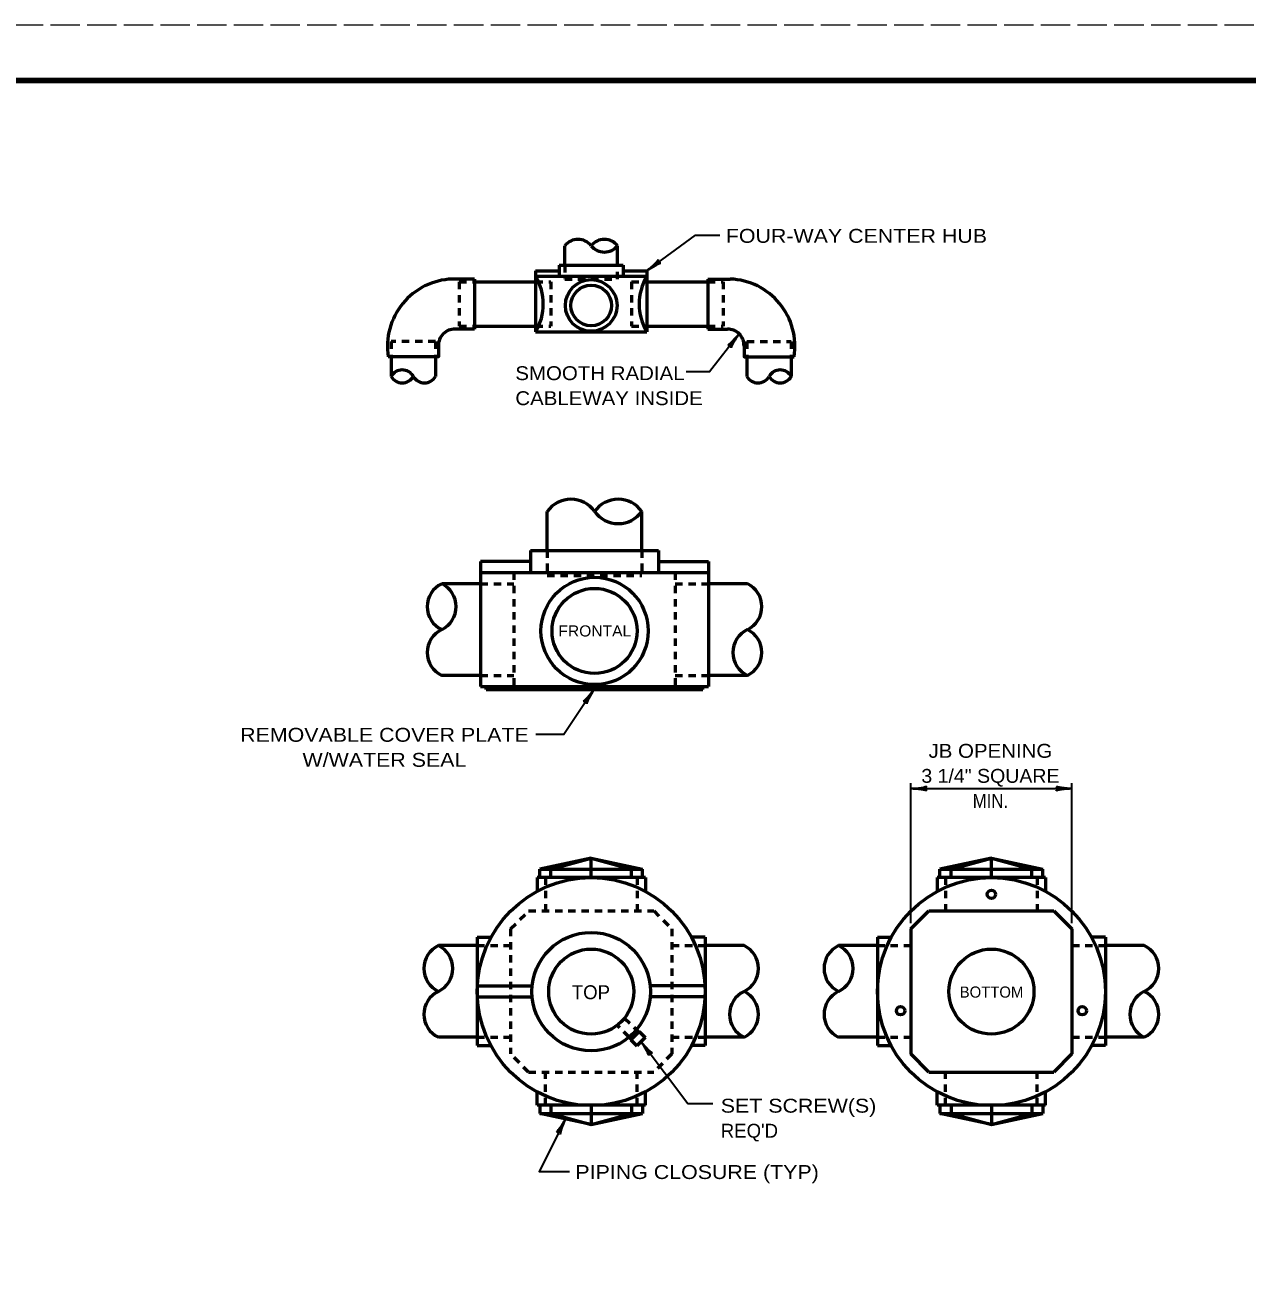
# Model space of a CAD drawing. Extents: x -295 to 385, y -102 to 338.
# Drawn here: x -75.4 to 144.5, y 114.2 to 338.4 of the extents above; entities that cross this region are included whole.
import ezdxf
from ezdxf.enums import TextEntityAlignment as Align

# ---------------------------------------------------------------- set-up
doc = ezdxf.new("R2010")
doc.units = 0
doc.header["$LTSCALE"] = 0.88
doc.linetypes.add('LONG_DASHED', pattern=[7.5, 6, -1.5])
doc.linetypes.add('SHORT_DASHED', pattern=[2.7, 1.5, -1.2])
doc.layers.add('1', color=7, linetype='Continuous', lineweight=53)
doc.layers.add('61', color=7, linetype='Continuous', lineweight=35)

msp = doc.modelspace()

# ---------------------------------------------------------------- linework, layer by layer
at = {"layer": '1'}
for p, q in [((21.7247, 295.2439), (21.7247, 298.7439)), ((31.2247, 295.2439), (31.2247, 298.7439)), ((16.4747, 294.2439), (16.4747, 283.2439)), ((16.4747, 294.2439), (20.7247, 294.2439)), ((20.7247, 295.2439), (32.2247, 295.2439)), ((20.7247, 295.2439), (20.7247, 293.2439)), ((32.2247, 295.2439), (32.2247, 293.2439)), ((32.2247, 294.2439), (36.4747, 294.2439)), ((36.4747, 294.2439), (36.4747, 283.2439)), ((5.4747, 292.7439), (1.4747, 292.7439)), ((5.4747, 292.7439), (5.4747, 283.7439)), ((5.4747, 292.2439), (16.4747, 292.2439)), ((16.4747, 293.2439), (36.4747, 293.2439)), ((36.4747, 292.2439), (47.4747, 292.2439)), ((47.4747, 292.7439), (47.4747, 283.7439)), ((47.4747, 292.7439), (51.4747, 292.7439)), ((5.4747, 283.7439), (1.9747, 283.7439)), ((5.4747, 284.2439), (16.4747, 284.2439)), ((16.4747, 283.2439), (36.4747, 283.2439)), ((36.4747, 284.2439), (47.4747, 284.2439)), ((47.4747, 283.7439), (50.9747, 283.7439)), ((-9.5253, 278.7439), (-9.5253, 275.2439)), ((-1.5253, 278.7439), (-1.5253, 275.2439)), ((54.4747, 278.7439), (54.4747, 275.2439)), ((62.4747, 278.7439), (62.4747, 275.2439)), ((18.5817, 243.9539), (18.5817, 250.9539)), ((35.5817, 243.9539), (35.5817, 250.9539)), ((15.5817, 243.9539), (38.5817, 243.9539)), ((15.5817, 243.9539), (15.5817, 239.9539)), ((38.5817, 243.9539), (38.5817, 239.9539)), ((15.5817, 241.9539), (6.5817, 241.9539)), ((6.5817, 241.9539), (6.5817, 219.4539)), ((38.5817, 241.9539), (47.5817, 241.9539)), ((47.5817, 241.9539), (47.5817, 219.4539)), ((6.5817, 237.9539), (-0.4183, 237.9539)), ((6.5817, 239.9539), (47.5817, 239.9539)), ((54.5817, 237.9539), (47.5817, 237.9539)), ((6.5817, 221.4539), (-0.4183, 221.4539)), ((54.5817, 221.4539), (47.5817, 221.4539)), ((6.5817, 219.4539), (47.5817, 219.4539)), ((7.5817, 218.9539), (7.5817, 219.4539)), ((7.5817, 218.9539), (46.5817, 218.9539)), ((46.5817, 218.9539), (46.5817, 219.4539)), ((26.4747, 188.5908), (35.7247, 186.5908)), ((98.4747, 188.5908), (107.7247, 186.5908)), ((17.2247, 185.0908), (17.2247, 186.5908)), ((17.2247, 186.5908), (35.7247, 186.5908)), ((19.2247, 185.0908), (19.2247, 186.5908)), ((33.7247, 185.0908), (33.7247, 186.5908)), ((35.7247, 185.0908), (35.7247, 186.5908)), ((89.2247, 185.0908), (89.2247, 186.5908)), ((89.2247, 186.5908), (107.7247, 186.5908)), ((91.2247, 185.0908), (91.2247, 186.5908)), ((105.7247, 185.0908), (105.7247, 186.5908)), ((107.7247, 185.0908), (107.7247, 186.5908)), ((16.7247, 185.0908), (16.7247, 182.6437)), ((36.2247, 185.0908), (16.7247, 185.0908)), ((36.2247, 185.0908), (36.2247, 182.6038)), ((88.7247, 185.0908), (88.7247, 182.6437)), ((108.2247, 185.0908), (88.7247, 185.0908)), ((108.2247, 185.0908), (108.2247, 182.6038)), ((83.9747, 175.8777), (87.2247, 179.0908)), ((87.2247, 179.0908), (109.7247, 179.0908)), ((109.7247, 179.0908), (112.9747, 175.8777)), ((83.9747, 175.8777), (83.9747, 153.3777)), ((112.9747, 175.8777), (112.9747, 153.3777)), ((5.9747, 172.8777), (-1.0253, 172.8777)), ((5.9747, 174.3777), (5.9747, 154.8777)), ((5.9747, 174.3777), (8.4617, 174.3777)), ((46.9747, 174.3777), (44.4877, 174.3777)), ((46.9747, 174.3777), (46.9747, 154.8777)), ((53.9747, 172.8777), (46.9747, 172.8777)), ((77.9747, 172.8777), (70.9747, 172.8777)), ((77.9747, 174.3777), (77.9747, 154.8777)), ((77.9747, 174.3777), (80.4617, 174.3777)), ((118.9747, 174.3777), (116.4877, 174.3777)), ((118.9747, 174.3777), (118.9747, 154.8777)), ((125.9747, 172.8777), (118.9747, 172.8777)), ((5.9747, 165.6277), (15.8752, 165.6277)), ((46.9747, 165.6277), (37.0741, 165.6277)), ((5.9747, 163.6277), (15.8683, 163.6277)), ((46.9747, 163.6277), (37.081, 163.6277)), ((35.1181, 157.4104), (33.6258, 155.9013)), ((34.6189, 157.7283), (35.0303, 157.3216)), ((35.1181, 157.4104), (36.1848, 156.3558)), ((5.9747, 156.3777), (-1.0253, 156.3777)), ((5.9747, 154.8777), (8.4218, 154.8777)), ((33.7137, 155.9902), (33.2911, 156.408)), ((33.6258, 155.9013), (34.6925, 154.8467)), ((36.1848, 156.3558), (34.6925, 154.8467)), ((46.9747, 154.8777), (44.5275, 154.8777)), ((53.9747, 156.3777), (46.9747, 156.3777)), ((77.9747, 156.3777), (70.9747, 156.3777)), ((77.9747, 154.8777), (80.4218, 154.8777)), ((118.9747, 154.8777), (116.5275, 154.8777)), ((125.9747, 156.3777), (118.9747, 156.3777)), ((87.2247, 150.0908), (83.9747, 153.3777)), ((112.9747, 153.3777), (109.7247, 150.0908)), ((87.2247, 150.0908), (109.7247, 150.0908)), ((16.7247, 144.1645), (16.7247, 146.6117)), ((36.2247, 144.1645), (36.2247, 146.6515)), ((88.7247, 144.1645), (88.7247, 146.6117)), ((108.2247, 144.1645), (108.2247, 146.6515)), ((36.2247, 144.1645), (16.7247, 144.1645)), ((17.2247, 144.1645), (17.2247, 142.6645)), ((19.2247, 144.1645), (19.2247, 142.6645)), ((33.7247, 144.1645), (33.7247, 142.6645)), ((35.7247, 144.1645), (35.7247, 142.6645)), ((108.2247, 144.1645), (88.7247, 144.1645)), ((89.2247, 144.1645), (89.2247, 142.6645)), ((91.2247, 144.1645), (91.2247, 142.6645)), ((105.7247, 144.1645), (105.7247, 142.6645)), ((107.7247, 144.1645), (107.7247, 142.6645)), ((17.2247, 142.6645), (35.7247, 142.6645)), ((26.4747, 140.6645), (35.7247, 142.6645)), ((89.2247, 142.6645), (107.7247, 142.6645)), ((98.4747, 140.6645), (107.7247, 142.6645))]:
    msp.add_line(p, q, dxfattribs=at)
at = {"layer": '1', "linetype": 'SHORT_DASHED'}
for p, q in [((21.7247, 295.2439), (21.7247, 292.7439)), ((31.2247, 292.7439), (31.2247, 295.2439)), ((2.7247, 292.2439), (2.7247, 284.2439)), ((2.7247, 292.2439), (5.4747, 292.2439)), ((16.4747, 292.2439), (19.2247, 292.2439)), ((19.2247, 292.2439), (19.2247, 284.2439)), ((21.7247, 292.7439), (31.2247, 292.7439)), ((33.7247, 292.2439), (33.7247, 284.2439)), ((33.7247, 292.2439), (36.4747, 292.2439)), ((47.4747, 292.2439), (50.2247, 292.2439)), ((50.2247, 292.2439), (50.2247, 284.2439)), ((2.7247, 284.2439), (5.4747, 284.2439)), ((16.4747, 284.2439), (19.2247, 284.2439)), ((33.7247, 284.2439), (36.4747, 284.2439)), ((47.4747, 284.2439), (50.2247, 284.2439)), ((-1.5253, 281.4939), (-9.5253, 281.4939)), ((-9.5253, 281.4939), (-9.5253, 278.7439)), ((-1.5253, 281.4939), (-1.5253, 278.7439)), ((54.4747, 281.4939), (62.4747, 281.4939)), ((54.4747, 281.4939), (54.4747, 278.7439)), ((62.4747, 281.4939), (62.4747, 278.7439)), ((18.5817, 243.9539), (18.5817, 239.4539)), ((35.5817, 243.9539), (35.5817, 239.4539)), ((6.5817, 237.9539), (12.5817, 237.9539)), ((12.5817, 239.9539), (12.5817, 219.4539)), ((18.5817, 239.4539), (35.5817, 239.4539)), ((41.5817, 239.9539), (41.5817, 219.4539)), ((41.5817, 237.9539), (47.5817, 237.9539)), ((6.5817, 221.4539), (12.5817, 221.4539)), ((41.5817, 221.4539), (47.5817, 221.4539)), ((18.2247, 185.0908), (18.2247, 179.0908)), ((34.7247, 185.0908), (34.7247, 179.0908)), ((90.2247, 185.0908), (90.2247, 179.0908)), ((106.7247, 185.0908), (106.7247, 179.0908)), ((11.9747, 175.8777), (15.2247, 179.0908)), ((15.2247, 179.0908), (37.7247, 179.0908)), ((37.7247, 179.0908), (40.9747, 175.8777)), ((11.9747, 175.8777), (11.9747, 153.3777)), ((40.9747, 175.8777), (40.9747, 153.3777)), ((5.9747, 172.8777), (11.9747, 172.8777)), ((40.9747, 172.8777), (46.9747, 172.8777)), ((77.9747, 172.8777), (83.9747, 172.8777)), ((112.9747, 172.8777), (118.9747, 172.8777)), ((32.4762, 159.8469), (34.6189, 157.7283)), ((33.2911, 156.408), (31.1439, 158.5311)), ((5.9747, 156.3777), (11.9747, 156.3777)), ((40.9747, 156.3777), (46.9747, 156.3777)), ((77.9747, 156.3777), (83.9747, 156.3777)), ((112.9747, 156.3777), (118.9747, 156.3777)), ((15.2247, 150.0908), (11.9747, 153.3777)), ((40.9747, 153.3777), (37.7247, 150.0908)), ((15.2247, 150.0908), (37.7247, 150.0908)), ((18.2247, 144.1645), (18.2247, 150.1645)), ((34.7247, 144.1645), (34.7247, 150.1645)), ((90.2247, 144.1645), (90.2247, 150.1645)), ((106.7247, 144.1645), (106.7247, 150.1645))]:
    msp.add_line(p, q, dxfattribs=at)
at = {"layer": '1', "lineweight": 35}
for p, q in [((83.9747, 176.8777), (83.9747, 202.1024)), ((112.9747, 176.8777), (112.9747, 202.1024)), ((83.9747, 201.1024), (112.9747, 201.1024))]:
    msp.add_line(p, q, dxfattribs=at)
for points in [[(36.4747, 294.2439), (45.2244, 300.6234), (49.647, 300.6234)], [(53.1085, 282.8777), (47.7674, 276.0701), (43.566, 276.0701)], [(26.9627, 218.9539), (21.5255, 210.8045), (16.5196, 210.8045)], [(35.4387, 155.6012), (43.8568, 144.4872), (48.3316, 144.4872)], [(21.8497, 141.6645), (17.1263, 132.2367), (22.5431, 132.2367)]]:
    msp.add_lwpolyline(points, dxfattribs=at)
at = {"layer": '1'}
for points in [[(-1.0253, 280.7439), (-1.0253, 278.7439), (-10.0253, 278.7439)], [(53.9747, 280.7439), (53.9747, 278.7439), (62.9747, 278.7439)], [(26.4747, 185.0908), (26.4747, 188.5908), (17.2247, 186.5908)], [(19.2247, 186.5908), (26.4747, 188.5908), (33.7247, 186.5908)], [(98.4747, 185.0908), (98.4747, 188.5908), (89.2247, 186.5908)], [(91.2247, 186.5908), (98.4747, 188.5908), (105.7247, 186.5908)], [(26.4747, 144.1645), (26.4747, 140.6645), (17.2247, 142.6645)], [(98.4747, 144.1645), (98.4747, 140.6645), (89.2247, 142.6645)], [(19.2247, 142.6645), (26.4747, 140.6645), (33.7247, 142.6645)], [(91.2247, 142.6645), (98.4747, 140.6645), (105.7247, 142.6645)]]:
    msp.add_lwpolyline(points, dxfattribs=at)
for centre, radius in [((26.4747, 287.9939), 4.65), ((26.4747, 287.9939), 3.65), ((27.0817, 229.4539), 9.65), ((27.0817, 229.4539), 7.65), ((26.4747, 164.5908), 20.5), ((98.4747, 164.5908), 20.5), ((98.4747, 182.0908), 0.75), ((26.4747, 164.5908), 10.65), ((26.4747, 164.5908), 7.65), ((98.4747, 164.5908), 7.65), ((82.1352, 161.1488), 0.75), ((114.8142, 161.1488), 0.75)]:
    msp.add_circle(centre, radius, dxfattribs=at)
for centre, radius, start, end in [((24.0997, 296.8358), 3.0465, 38.77886, 141.22114), ((28.8497, 296.8358), 3.0465, 38.77886, 141.22114), ((28.8497, 300.652), 3.0465, 218.77886, 321.22114), ((1.9115, 280.6619), 12.0899, 92.07061, 189.12807), ((8.0713, 288.2439), 9.7784, 329.2475, 30.7525), ((44.8781, 288.2439), 9.7784, 149.2475, 210.7525), ((51.0378, 280.6619), 12.0899, 350.87193, 87.92939), ((1.9326, 280.786), 2.9583, 89.18565, 180.81435), ((51.0167, 280.786), 2.9583, 359.18565, 90.81435), ((-7.5253, 274.0939), 2.3071, 29.89897, 150.10103), ((60.4747, 274.0939), 2.3071, 29.89897, 150.10103), ((-7.5253, 276.3939), 2.3071, 209.89897, 330.10103), ((-3.5253, 276.3939), 2.3071, 209.89897, 330.10103), ((56.4747, 276.3939), 2.3071, 209.89897, 330.10103), ((60.4747, 276.3939), 2.3071, 209.89897, 330.10103), ((22.8317, 247.9285), 5.2169, 35.44593, 144.55407), ((31.3317, 247.9285), 5.2169, 35.44593, 144.55407), ((31.3317, 253.9794), 5.2169, 215.44593, 324.55407), ((1.5408, 233.8289), 4.5666, 115.40389, 244.59611), ((-2.3773, 233.8289), 4.5666, 295.40389, 64.59611), ((52.6227, 233.8289), 4.5666, 295.40389, 64.59611), ((1.5408, 225.5789), 4.5666, 115.40389, 244.59611), ((56.5408, 225.5789), 4.5666, 115.40389, 244.59611), ((52.6227, 225.5789), 4.5666, 295.40389, 64.59611), ((0.9337, 168.7527), 4.5666, 115.40389, 244.59611), ((-2.9844, 168.7527), 4.5666, 295.40389, 64.59611), ((52.0156, 168.7527), 4.5666, 295.40389, 64.59611), ((72.9337, 168.7527), 4.5666, 115.40389, 244.59611), ((69.0156, 168.7527), 4.5666, 295.40389, 64.59611), ((124.0156, 168.7527), 4.5666, 295.40389, 64.59611), ((0.9337, 160.5027), 4.5666, 115.40389, 244.59611), ((55.9337, 160.5027), 4.5666, 115.40389, 244.59611), ((52.0156, 160.5027), 4.5666, 295.40389, 64.59611), ((72.9337, 160.5027), 4.5666, 115.40389, 244.59611), ((127.9337, 160.5027), 4.5666, 115.40389, 244.59611), ((124.0156, 160.5027), 4.5666, 295.40389, 64.59611)]:
    msp.add_arc(centre, radius, start, end, dxfattribs=at)
at = {"layer": '1', "lineweight": 40}
for centre, major_axis, ratio, start_param, end_param in [((37.1936, 295.11), (-1.3509, -1.1782), 0.122415, 0.89635335, 3.14159265), ((37.5047, 294.7331), (-1.5227, -0.8929), 0.07063, 3.14071475, 5.41810995), ((52.2504, 282.1268), (1.2224, 1.2735), 0.07063, 3.14071475, 5.41810995), ((52.6523, 281.8487), (0.9794, 1.5013), 0.122415, 0.89635335, 3.14159265), ((26.1273, 218.1996), (1.121, 1.3988), 0.122415, 3.14159265, 5.38683196), ((26.5169, 217.9044), (0.8287, 1.5586), 0.07063, 0.86507535, 3.14247055), ((85.0952, 200.8908), (-1.7565, 0.1757), 0.07063, 3.14071475, 5.41810995), ((85.0952, 200.8908), (-1.7565, 0.1757), 0.07063, 3.14071475, 5.41810995), ((85.0659, 201.3787), (-1.7857, -0.1562), 0.122415, 0.89635335, 3.14159265), ((85.0659, 201.3787), (-1.7857, -0.1562), 0.122415, 0.89635335, 3.14159265), ((111.8835, 200.8261), (1.7857, 0.1562), 0.122415, 0.89635335, 3.14159265), ((111.8542, 201.314), (1.7565, -0.1757), 0.07063, 3.14071475, 5.41810995), ((35.9465, 154.5803), (-0.9205, 1.5062), 0.07063, 3.14071475, 5.41810995), ((36.3178, 154.8982), (-1.2027, 1.3292), 0.122415, 0.89635335, 3.14159265), ((21.1586, 140.7575), (0.9438, 1.4917), 0.07063, 3.14071475, 5.41810995), ((21.6079, 140.5651), (0.6603, 1.6665), 0.122415, 0.89635335, 3.14159265)]:
    msp.add_ellipse(centre, major_axis=major_axis, ratio=ratio, start_param=start_param, end_param=end_param, dxfattribs=at)
at = {"layer": '61', "linetype": 'LONG_DASHED', "lineweight": 13}
msp.add_line((-295.2093, 338.4444), (384.8107, 338.4444), dxfattribs=at)
at = {"layer": '61', "lineweight": 158}
msp.add_lwpolyline([(373.8307, 328.4444), (-265.2093, 328.4444), (-265.2093, -91.5756)], dxfattribs=at)

# ---------------------------------------------------------------- texts
at = {"layer": '1'}
for s, height, width, p in [('FOUR-WAY CENTER HUB', 2.5, 1.15, (74.1923, 299.2627)), ('FRONTAL', 2, 1.05, (27.1205, 228.4601)), ('REMOVABLE COVER PLATE', 2.5, 1.15, (-10.7245, 209.5248)), ('JB OPENING', 2.5, 1.1, (98.2946, 206.6432)), ('W/WATER SEAL', 2.5, 1.15, (-10.7245, 205.0248)), ('3 1/4" SQUARE', 2.5, 1.05, (98.2946, 202.1432)), ('MIN.', 2.5, 0.9, (98.2946, 197.6432)), ('PIPING CLOSURE (TYP)', 2.5, 1.15, (45.5286, 130.8908))]:
    msp.add_text(s, height=height, dxfattribs=dict(at, width=width)).set_placement(p, align=Align.CENTER)
for s, width, p in [('SMOOTH RADIAL', 1.1, (12.8289, 274.5654)), ('CABLEWAY INSIDE', 1.1, (12.8289, 270.0654)), ('SET SCREW(S)', 1.15, (49.7892, 142.8207))]:
    msp.add_text(s, height=2.5, dxfattribs=dict(at, width=width)).set_placement(p)
for s, height, p in [('TOP', 2.5, (26.4235, 163.2307)), ('BOTTOM', 2, (98.4955, 163.5122))]:
    msp.add_text(s, height=height, dxfattribs=at).set_placement(p, align=Align.CENTER)
msp.add_text("REQ'D", height=2.5, dxfattribs=at).set_placement((49.7892, 138.3207))

doc.saveas('drawing.dxf')
